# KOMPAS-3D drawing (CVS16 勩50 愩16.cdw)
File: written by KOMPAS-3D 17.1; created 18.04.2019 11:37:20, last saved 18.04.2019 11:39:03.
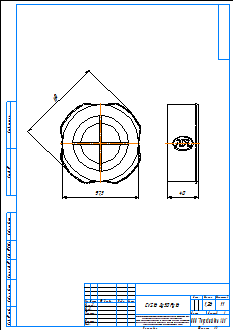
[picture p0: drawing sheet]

Sheet 1: A3, portrait

Title block, sheet 1: name: CVS16 Ду50 Ру16; material: Внимание! Данный продукт является объектом авторского права ООО «Торговый Дом АДЛ». / Запрещается изменение, копирование, распространение / (в том числе путем копирования на другие сайты и ресурсы в Интернете) / или любое иное использование информации и объектов без предварительного / согласия правообладателя (ООО «Торговый Дом АДЛ»).; mass: 1,26; sheets: 1; organisation: ООО "Торговый дом АДЛ"; sheet format: A3

Views: Вид 1, Проекционный вид 2
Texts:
  user
Dimensions and other numbers on the sheet: 110; 97,5; 40; 1:1; 1; 1,26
